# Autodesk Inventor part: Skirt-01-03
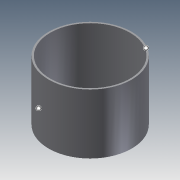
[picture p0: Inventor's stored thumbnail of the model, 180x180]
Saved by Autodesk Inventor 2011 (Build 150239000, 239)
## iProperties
Created: 2010-06
Part Number: Skirt-01-03
Document SubType Name: Modeling
Designer: mklassen
Density: 1 g/cm^3
OD: 36.000 in
THK: 0.500 in
LEN: 1.500 ft
SKVOFS: -6.000 in
Author: mklassen
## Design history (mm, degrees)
sketch "skSkirt"
  geometry: C1 r 469.9 at (0, 0); C2 r 457.2 at (0, 0); 1 further point
  constraints: 2 centre point, 1 coincident
  dimensions: "d0" = 914.4 diameter of C2 (derived); "d1" = 12.7 radial gap between concentric circles of C1 C2 (derived)
extrude "Extrusion1" new body sketch "skSkirt" stored distance "d2" = 457.2 (derived); taper "d3" = 0 deg
body "Solid1"
other parameters: "d4" = -152.4 (derived), "d5" = 0
